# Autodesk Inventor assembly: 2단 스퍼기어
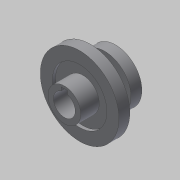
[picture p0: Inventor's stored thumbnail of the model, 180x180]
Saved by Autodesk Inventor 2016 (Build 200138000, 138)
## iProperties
Created: 2018-09
Part Number: 2단 스퍼기어
Document SubType Name: Assembly
Designer: MYS
Mass: 54.758 g
Surface Area: 207.624 cm^2
Volume: 54.758 cm^3
Density: 1 g/cm^3
Author: MYS
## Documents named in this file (2)
- C:\Users\MYS\Desktop\답안\2단 스퍼기어.iam
- C:\Users\MYS\Desktop\답안\2단 스퍼기어.ipt
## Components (1 placed, 1 different names)
1. 2단 스퍼기어:1
